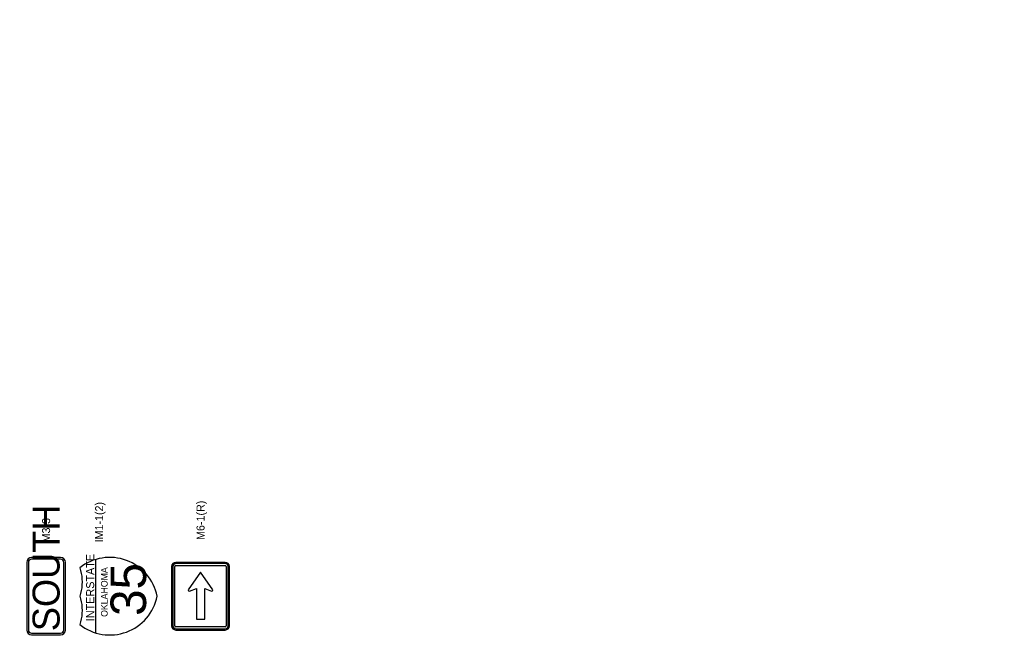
# Model space of a CAD drawing. Extents: x 2135767 to 2151731, y 141839 to 175894.
# Drawn here: x 2137980 to 2138549, y 170346 to 170711 of the extents above; entities that cross this region are included whole.
import ezdxf

# ---------------------------------------------------------------- set-up
doc = ezdxf.new("R2010")
doc.units = 0
doc.layers.add('PR_Phasing_Detour_1', color=7, linetype='Continuous')

msp = doc.modelspace()

# ---------------------------------------------------------------- linework, layer by layer
at = {"layer": 'PR_Phasing_Detour_1'}
for p, q in [((2137983.95, 170394.81), (2137983.95, 170355.43)), ((2137984.89, 170394.81), (2137984.89, 170355.43)), ((2138003.64, 170397.62), (2137986.76, 170397.62)), ((2138003.64, 170396.68), (2137986.76, 170396.68)), ((2138005.51, 170355.43), (2138005.51, 170394.81)), ((2138006.45, 170355.43), (2138006.45, 170394.81)), ((2138024.26, 170353.71), (2138024.26, 170396.55)), ((2138099.58, 170394.81), (2138070.82, 170394.81)), ((2138099.58, 170394.1), (2138070.82, 170394.1)), ((2138099.58, 170394.1), (2138070.82, 170394.1)), ((2138068.32, 170392.31), (2138068.32, 170357.92)), ((2138069.03, 170392.31), (2138069.03, 170357.92)), ((2138069.03, 170392.31), (2138069.03, 170357.92)), ((2138070.2, 170357.92), (2138070.2, 170392.31)), ((2138070.2, 170357.92), (2138070.2, 170392.31)), ((2138070.82, 170392.93), (2138099.58, 170392.93)), ((2138070.82, 170392.93), (2138099.58, 170392.93)), ((2138085.2, 170389.18), (2138078.01, 170378.79)), ((2138092.39, 170378.79), (2138085.2, 170389.18)), ((2138100.2, 170392.31), (2138100.2, 170357.92)), ((2138100.2, 170392.31), (2138100.2, 170357.92)), ((2138101.37, 170357.92), (2138101.37, 170392.31)), ((2138101.37, 170357.92), (2138101.37, 170392.31)), ((2138102.07, 170357.92), (2138102.07, 170392.31)), ((2138078.81, 170377.99), (2138082.8, 170379.59)), ((2138082.8, 170379.59), (2138082.8, 170361.76)), ((2138087.6, 170361.76), (2138087.6, 170379.59)), ((2138087.6, 170379.59), (2138091.59, 170377.99)), ((2138082.8, 170361.76), (2138087.6, 170361.76)), ((2138099.58, 170357.31), (2138070.82, 170357.31)), ((2138099.58, 170357.31), (2138070.82, 170357.31)), ((2138070.82, 170356.13), (2138099.58, 170356.13)), ((2138070.82, 170356.13), (2138099.58, 170356.13)), ((2138070.82, 170355.43), (2138099.58, 170355.43)), ((2137986.76, 170353.56), (2138003.64, 170353.56)), ((2137986.76, 170352.62), (2138003.64, 170352.62))]:
    msp.add_line(p, q, dxfattribs=at)
for points in [[(2138014.89, 170358.59), (2138016.33, 170357.52), (2138017.84, 170356.55), (2138019.4, 170355.68), (2138021.02, 170354.9), (2138022.69, 170354.24), (2138024.39, 170353.68), (2138026.12, 170353.23), (2138027.89, 170352.89), (2138029.66, 170352.66), (2138031.45, 170352.55), (2138033.25, 170352.55), (2138035.04, 170352.67), (2138036.82, 170352.9), (2138038.58, 170353.24), (2138040.31, 170353.7), (2138042.01, 170354.26), (2138043.68, 170354.93), (2138045.29, 170355.71), (2138046.86, 170356.59), (2138048.36, 170357.56), (2138049.8, 170358.63), (2138051.17, 170359.79), (2138052.46, 170361.04), (2138053.67, 170362.36), (2138054.79, 170363.76), (2138055.82, 170365.22), (2138056.76, 170366.75), (2138057.6, 170368.34), (2138058.33, 170369.98), (2138058.96, 170371.66), (2138059.48, 170373.37), (2138059.89, 170375.12), (2138059.48, 170376.86), (2138058.96, 170378.58), (2138058.33, 170380.26), (2138057.6, 170381.9), (2138056.76, 170383.48), (2138055.82, 170385.01), (2138054.79, 170386.48), (2138053.67, 170387.88), (2138052.46, 170389.2), (2138051.17, 170390.44), (2138049.8, 170391.6), (2138048.36, 170392.67), (2138046.86, 170393.65), (2138045.29, 170394.53), (2138043.68, 170395.3), (2138042.01, 170395.97), (2138040.31, 170396.54), (2138038.58, 170396.99), (2138036.82, 170397.34), (2138035.04, 170397.57), (2138033.25, 170397.68), (2138031.45, 170397.69), (2138029.66, 170397.57), (2138027.89, 170397.35), (2138026.12, 170397.01), (2138024.39, 170396.56), (2138022.69, 170396), (2138021.02, 170395.33), (2138019.4, 170394.56), (2138017.84, 170393.69), (2138016.33, 170392.72), (2138014.89, 170391.65), (2138015.33, 170390.03), (2138015.68, 170388.39), (2138015.93, 170386.73), (2138016.08, 170385.06), (2138016.13, 170383.38), (2138016.08, 170381.71), (2138015.93, 170380.04), (2138015.68, 170378.38), (2138015.33, 170376.74), (2138014.89, 170375.12), (2138015.33, 170373.5), (2138015.68, 170371.86), (2138015.93, 170370.2), (2138016.08, 170368.53), (2138016.13, 170366.85), (2138016.08, 170365.18), (2138015.93, 170363.5), (2138015.68, 170361.85), (2138015.33, 170360.2), (2138014.89, 170358.59)], [(2138085.2, 170389.18), (2138078.01, 170378.79)], [(2138092.39, 170378.79), (2138085.2, 170389.18)], [(2138078.81, 170377.99), (2138082.8, 170379.59), (2138082.8, 170361.76), (2138087.6, 170361.76), (2138087.6, 170379.59), (2138091.59, 170377.99)]]:
    msp.add_lwpolyline(points, dxfattribs=at)
msp.add_circle((2140069.54, 171591.41), 4302.23, dxfattribs=at)
for centre, radius, start, end in [((2137986.76, 170394.81), 2.81, 90, 180), ((2137986.76, 170394.81), 1.87, 90, 180), ((2138003.64, 170394.81), 2.81, 360, 90), ((2138003.64, 170394.81), 1.87, 360, 90), ((2138070.82, 170392.31), 2.49, 90, 180), ((2138070.82, 170392.31), 1.79, 90, 180), ((2138070.82, 170392.31), 1.79, 90, 180), ((2138099.58, 170392.31), 2.49, 360, 90), ((2138099.58, 170392.31), 1.79, 360, 90), ((2138099.58, 170392.31), 1.79, 360, 90), ((2138070.82, 170392.31), 0.618, 90, 180), ((2138070.82, 170392.31), 0.618, 90, 180), ((2138099.58, 170392.31), 0.618, 360, 90), ((2138099.58, 170392.31), 0.618, 360, 90), ((2138078.81, 170378.79), 0.799, 180, 270), ((2138078.81, 170378.79), 0.799, 180, 270), ((2138091.59, 170378.79), 0.799, 270, 360), ((2138091.59, 170378.79), 0.799, 270, 360), ((2137986.76, 170355.43), 2.81, 180, 270), ((2137986.76, 170355.43), 1.87, 180, 270), ((2138003.64, 170355.43), 1.87, 270, 360), ((2138003.64, 170355.43), 2.81, 270, 360), ((2138070.82, 170357.92), 2.49, 180, 270), ((2138070.82, 170357.92), 1.79, 180, 270), ((2138070.82, 170357.92), 1.79, 180, 270), ((2138070.82, 170357.92), 0.618, 180, 270), ((2138070.82, 170357.92), 0.618, 180, 270), ((2138099.58, 170357.92), 2.49, 270, 360), ((2138099.58, 170357.92), 1.79, 270, 360), ((2138099.58, 170357.92), 0.618, 270, 360), ((2138099.58, 170357.92), 1.79, 270, 360), ((2138099.58, 170357.92), 0.618, 270, 360)]:
    msp.add_arc(centre, radius, start, end, dxfattribs=at)

# ---------------------------------------------------------------- texts
for s, height, p in [('IM1-1(2)', 4.664, (2138028.45, 170406.43)), ('M6-1(R)', 4.664, (2138087.53, 170407.86)), ('SOUTH', 15.75, (2138003.07, 170354.75)), ('M3-3', 4.664, (2137997.53, 170406.43)), ('INTERSTATE', 4.704, (2138023.23, 170360.57)), ('OKLAHOMA', 3.812, (2138031.03, 170363.07)), ('35', 20.7, (2138053.46, 170363.63))]:
    msp.add_text(s, height=height, rotation=90, dxfattribs=at).set_placement(p)

doc.saveas('drawing.dxf')
